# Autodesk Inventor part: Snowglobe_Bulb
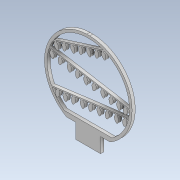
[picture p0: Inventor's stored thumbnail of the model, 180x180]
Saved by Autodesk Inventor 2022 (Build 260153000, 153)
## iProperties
Created: 2021-12
Part Number: Snowglobe_Bulb
Material: Generic
Document SubType Name: Modeling
Designer: allis
Density: 1 g/cm^3
Appearance: Default
Author: allis
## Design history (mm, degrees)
sketch "Sketch1"
  geometry: L1 (66.037, -12.603)-(57.925, -9.254); L2 (57.925, -9.254)-(46.111, -8.27); L3 (46.111, -8.27)-(35.078, -12.817); L4 (35.078, -12.817)-(27.168, -16.078); L5 (27.168, -16.078)-(20.88, -21.322); L6 (20.88, -21.322)-(16.072, -28.357); L7 (16.072, -28.357)-(16.096, -28.395); L8 (16.096, -28.395)-(16.12, -28.433); L9 (16.12, -28.433)-(16.144, -28.47); L10 (16.144, -28.47)-(32.745, -23.191); L11 (32.745, -23.191)-(49.347, -17.911); L12 (49.347, -17.911)-(66.037, -12.603); L13 (89.313, -61.465)-(89.694, -61.807); L14 (89.694, -61.807)-(89.511, -62.133); L15 (89.511, -62.133)-(89.463, -62.44); L16 (89.463, -62.44)-(89.397, -62.864); L17 (89.397, -62.864)-(89.354, -63.226); L18 (89.354, -63.226)-(89.739, -63.577); L19 (89.739, -63.577)-(90.187, -63.986); L20 (90.187, -63.986)-(90.321, -64.563); L21 (90.321, -64.563)-(90.209, -65.173); L22 (90.209, -65.173)-(89.937, -66.654); L23 (89.937, -66.654)-(89.226, -67.897); L24 (89.226, -67.897)-(88.13, -68.916); L25 (88.13, -68.916)-(87.475, -69.525); L26 (87.475, -69.525)-(86.774, -69.385); L27 (86.774, -69.385)-(86.376, -68.583); L28 (86.376, -68.583)-(85.798, -67.418); L29 (85.798, -67.418)-(85.577, -66.181); L30 (85.577, -66.181)-(85.673, -64.887); L31 (85.673, -64.887)-(85.735, -64.05); L32 (85.735, -64.05)-(86.016, -63.33); L33 (86.016, -63.33)-(86.848, -62.983); L34 (86.848, -62.983)-(87.16, -62.854); L35 (87.16, -62.854)-(87.297, -62.671); L36 (87.297, -62.671)-(87.374, -62.356); L37 (87.374, -62.356)-(87.515, -61.778); L38 (87.515, -61.778)-(87.458, -61.698); L39 (87.458, -61.698)-(86.884, -61.777); L40 (86.884, -61.777)-(85.879, -61.917); L41 (85.879, -61.917)-(84.872, -62.044); L42 (84.872, -62.044)-(83.866, -62.175); L43 (83.866, -62.175)-(82.734, -62.322); L44 (82.734, -62.322)-(81.602, -62.465); L45 (81.602, -62.465)-(80.471, -62.617); L46 (80.471, -62.617)-(80.324, -62.637); L47 (80.324, -62.637)-(80.147, -62.642); L48 (80.147, -62.642)-(80.078, -62.818); L49 (80.078, -62.818)-(79.961, -63.115); L50 (79.961, -63.115)-(80.283, -63.95); L51 (80.283, -63.95)-(80.572, -64.098); L52 (80.572, -64.098)-(81.193, -64.417); L53 (81.193, -64.417)-(81.577, -64.912); L54 (81.577, -64.912)-(81.665, -65.609); L55 (81.665, -65.609)-(81.853, -67.087); L56 (81.853, -67.087)-(81.537, -68.471); L57 (81.537, -68.471)-(80.828, -69.767); L58 (80.828, -69.767)-(80.397, -70.555); L59 (80.397, -70.555)-(79.7, -70.647); L60 (79.7, -70.647)-(79.063, -70.011); L61 (79.063, -70.011)-(78.063, -69.013); L62 (78.063, -69.013)-(77.47, -67.798); L63 (77.47, -67.798)-(77.202, -66.421); L64 (77.202, -66.421)-(77.074, -65.765)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; 1 further point
  constraints: 6 other
extrude "Extrusion1" new body sketch "Sketch1" distance "d0" = 3.175; taper "d1" = 0 deg
body "Solid1"
